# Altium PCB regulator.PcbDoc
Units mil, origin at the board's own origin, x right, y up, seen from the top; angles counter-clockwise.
Board outline 6000 x 4000 mil, 2 copper layers (Top Layer, Bottom Layer); 60 components, 45 nets, 228 pads, 31 vias.
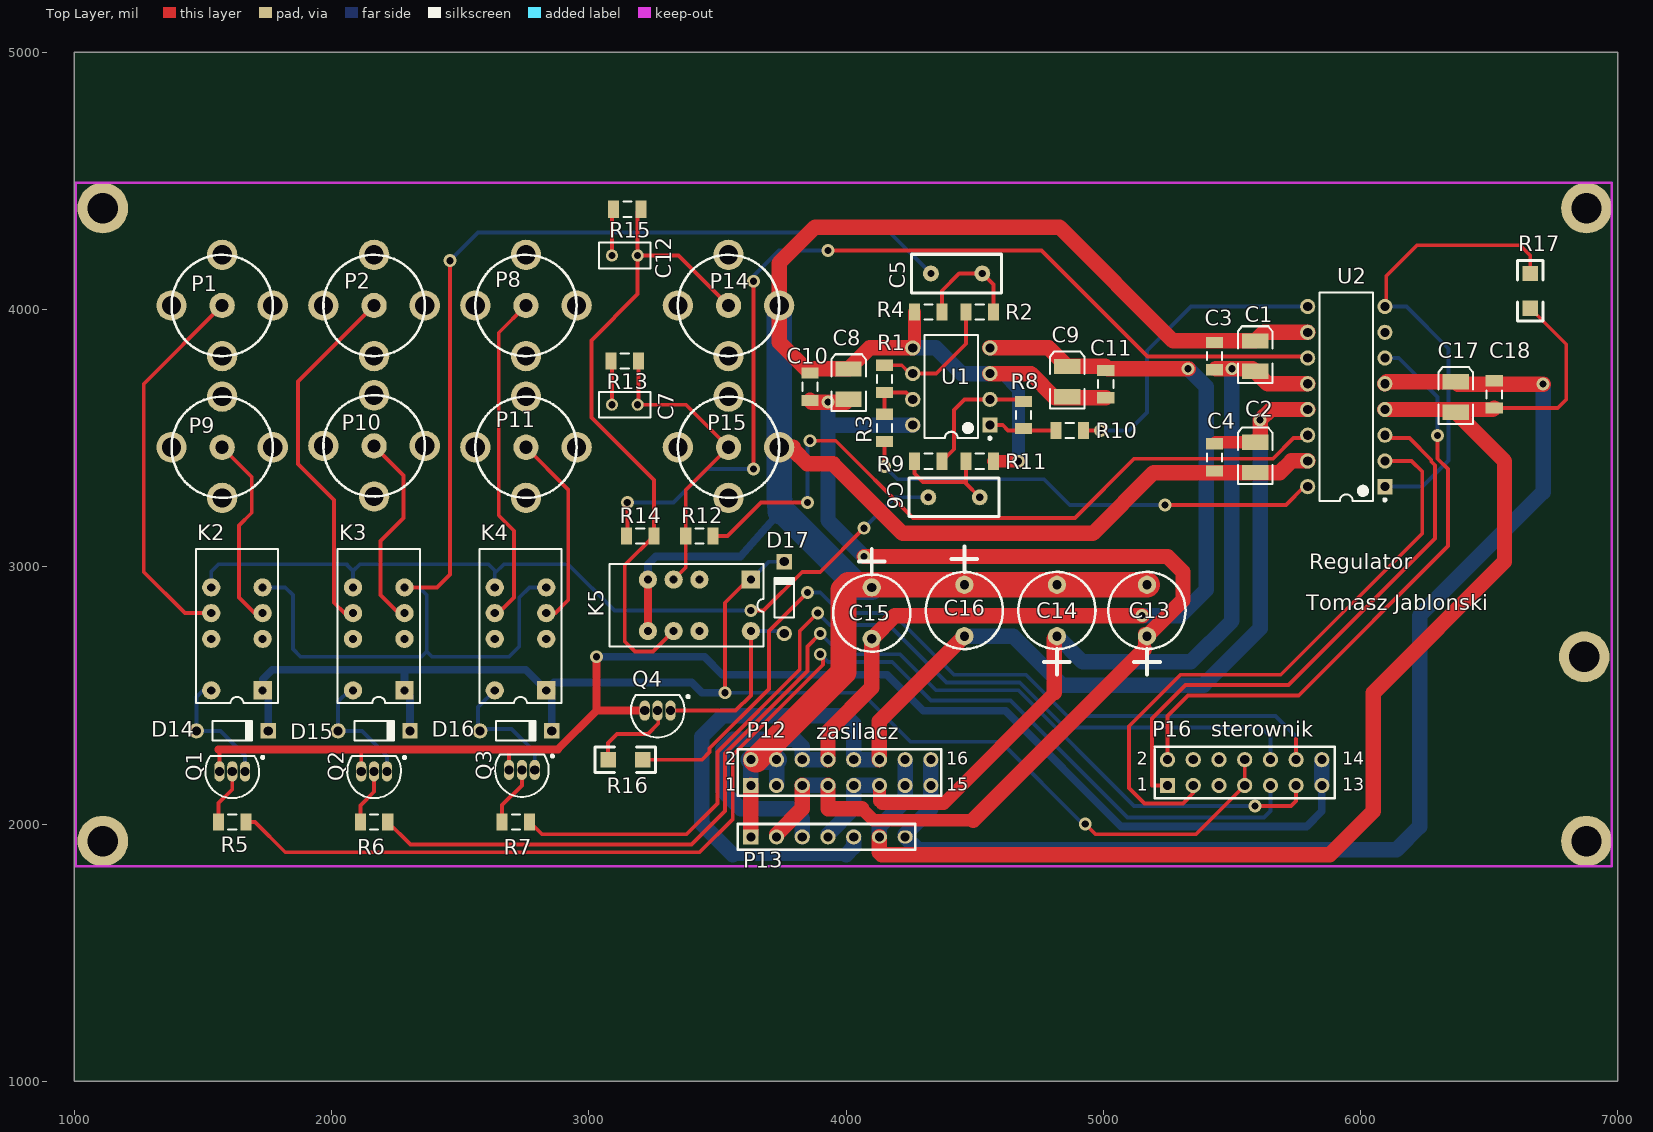
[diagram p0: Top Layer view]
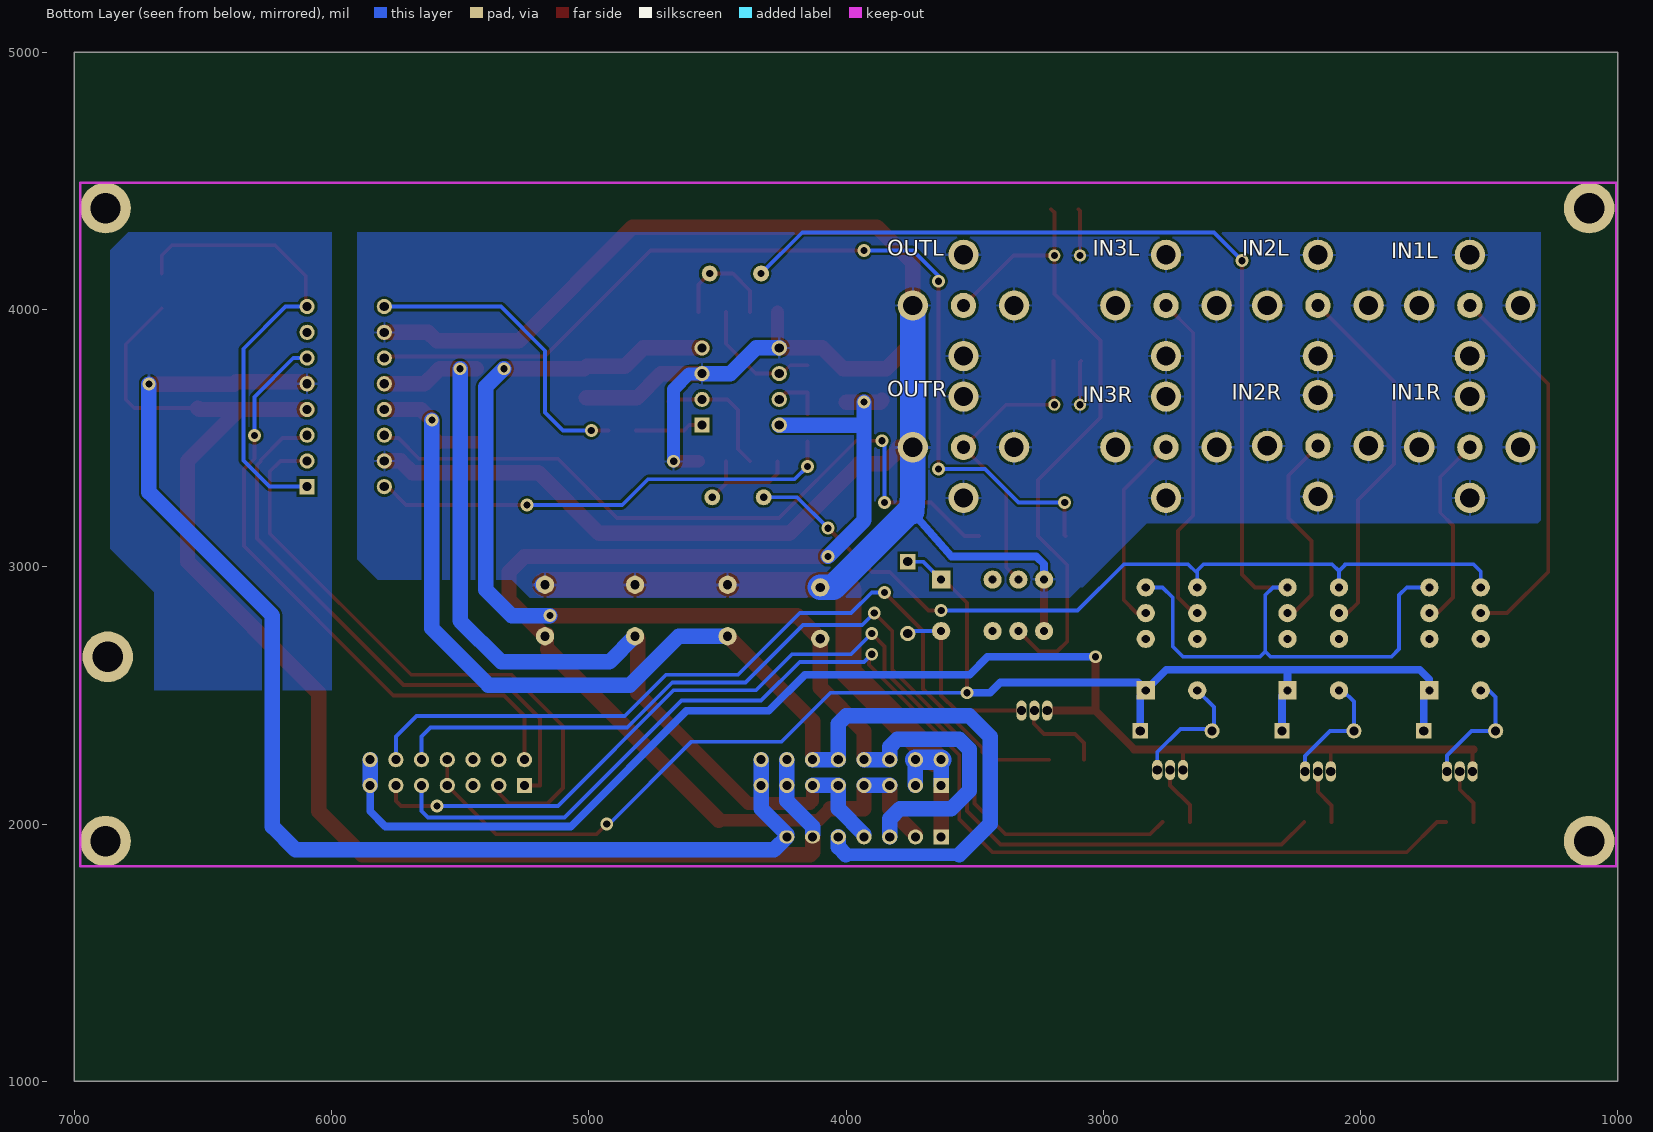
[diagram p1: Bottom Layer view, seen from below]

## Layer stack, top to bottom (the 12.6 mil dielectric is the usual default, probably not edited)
Top Solder: solder mask 0.4, Solder Resist, Dk 3.5
Top Layer: signal copper 1.4
Dielectric 1: dielectric 12.6, FR-4, Dk 4.8
Bottom Layer: signal copper 1.4
Bottom Solder: solder mask 0.4, Solder Resist, Dk 3.5

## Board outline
1000,1000 7000,1000 7000,5000 1000,5000

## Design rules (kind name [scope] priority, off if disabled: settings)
Clearance [All] p1: gap=10
PolygonConnect [All] p1: connectstyle=Relief reliefconductorwidth=10 reliefentries=4 polygonreliefangle="90 Angle" airgapwidth=10
RoomDefinition regulator [InComponentClass('regulator')] p1: confinementstyle=ConfineIn formatcopy=TRUE lockcomponents=FALSE outline 0,0 2000,0 2000,1000 0,1000
RoutingVias [All] p1: holewidth=28 width=50 viastyle="Through Hole" minholewidth=28 minwidth=50 maxholewidth=28 maxwidth=50
SolderMaskExpansion [All] p1: expansion=4
Width [All] p1: maxlimit=15 minlimit=15 preferedwidth=15
30 further rules are at their usual default settings.

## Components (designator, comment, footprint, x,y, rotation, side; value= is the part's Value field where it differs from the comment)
C1 "" 3.5X2.8X1.9 5590.55,3818.9 r90 top
C2 "" 3.5X2.8X1.9 5590.55,3425.2 r90 top
C3 "Cap" C1206 5433.07,3818.9 r90 top
C4 "Cap" C1206 5433.07,3425.2 r270 top
C5 "Cap" RAD0.2 4330,4140 r0 top
C6 "Cap" RAD0.2 4320,3270 r0 top
C7 "Cap" RAD-0.1 3140,3630 r0 top
C8 "" 3.5X2.8X1.9 4010,3710 r90 top
C9 "" 3.5X2.8X1.9 4860,3720 r90 top
C10 "Cap" C1206 3860,3700 r90 top
C11 "Cap" C1206 5010,3710 r270 top
C12 "Cap" RAD-0.1 3140,4210 r0 top
C13 "" RB.2/.3 5170,2730 r90 top
C14 "" RB.2/.3 4820,2730 r90 top
C15 "" RB.2/.3 4100,2920 r270 top
C16 "" RB.2/.3 4460,2930 r270 top
C17 "" 3.5X2.8X1.9 6370,3660 r90 top
C18 "Cap" C1206 6520,3670 r90 top
D14 "1N4148" DO-35 1614.17,2362.2 r0 top
D15 "1N4148" DO-35 2165.35,2362.2 r0 top
D16 "1N4148" DO-35 2716.54,2362.2 r0 top
D17 "1N4148" DO-35 3760,2880 r90 top
K2 "Relay-DPDT" Axicom_rel 1732.28,2519.68 r180 top
K3 "Relay-DPDT" Axicom_rel 2283.46,2519.68 r180 top
K4 "Relay-DPDT" Axicom_rel 2834.65,2519.68 r180 top
K5 "Relay-DPDT" Axicom_rel 3630,2950 r270 top
P1 "BNC" RCA_P 1574.8,4015.75 r0 top
P2 "BNC" RCA_P 2165.35,4015.75 r0 top
P8 "BNC" RCA_P 2755.91,4015.75 r0 top
P9 "BNC" RCA_P 1574.8,3464.57 r0 top
P10 "BNC" RCA_P 2165.35,3470 r0 top
P11 "BNC" RCA_P 2755.91,3464.57 r0 top
P12 "zasilacz" HDR2X8 3630,2150 r0 top
P13 "regulator" HDR1X7 3630,1950 r0 top
P14 "BNC" RCA_P 3543.31,4015.75 r0 top
P15 "BNC" RCA_P 3543.31,3464.57 r0 top
P16 "sterownik" HDR2X7 5250,2150 r0 top
Q1 "NPN" TO-226-AA 1614.17,2204.72 r90 top
Q2 "NPN" TO-226-AA 2165.35,2204.72 r90 top
Q3 "NPN" TO-226-AA 2740,2210 r90 top
Q4 "NPN" TO-226-AA 3267.72,2440.94 r90 top
R1 "Res2" C1206 4150,3730 r270 top
R2 "Res2" C1206 4520,3990 r180 top
R3 "Res2" C1206 4150,3540 r270 top
R4 "Res2" C1206 4320,3990 r0 top
R5 "Res2" C1206 1614.17,2007.87 r180 top
R6 "Res2" C1206 2165.35,2007.87 r180 top
R7 "Res2" C1206 2716.54,2007.87 r180 top
R8 "Res2" C1206 4690,3590 r270 top
R9 "Res2" C1206 4320,3410 r0 top
R10 "Res2" C1206 4870,3530 r0 top
R11 "Res2" C1206 4520,3410 r180 top
R12 "Res2" C1206 3430,3120 r0 top
R13 "Res2" C1206 3140,3800 r0 top
R14 "Res2" C1206 3200,3120 r180 top
R15 "Res2" C1206 3150,4390 r0 top
R16 "" 1206 3210,2250 r180 top
R17 "" 1206 6660,4140 r270 top
U1 "OPA2134PA" TI-P8 4409.45,3700.79 r180 top
U2 "PGA2311" DIP16 5944.88,3661.42 r180 top

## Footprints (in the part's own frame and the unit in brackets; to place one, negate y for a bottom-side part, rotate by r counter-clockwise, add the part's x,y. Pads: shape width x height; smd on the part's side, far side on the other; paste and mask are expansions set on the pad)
3.5X2.8X1.9 [mm] "SM LED; 2 C-Bend Leads; Body 3.5 x 2.8 x 1.9 mm, inc leads (LxWxH typ)"
  rect 1.5x2.6 smd: 1(-1.5,0) 2(1.5,0)
  silkscreen extent -2.65,-1.7 2.95,1.7
1206 [mil]
  rect 60x60 smd: 1(0,0) 2(135,0)
  silkscreen extent -50,-50 185,50
Axicom_rel [mm]
  round 1.8 hole 0.8: 1(0,-7.62) 2(0,-5.08) 3(0,-10.16) 4(5.08,-7.62) 5(5.08,-5.08) 6(5.08,-10.16) 8(5.08,0)
  rect 1.8x1.8 hole 0.8: 7(0,0)
  silkscreen extent -1.52,-13.97 6.6,1.27
C1206 [mm] "Chip Capacitor, Body 3.2x1.6mm, IPC High Density"
  rect 1.1x1.7 smd: 1(-1.35,0) 2(1.35,0)
  silkscreen extent -0.4,-0.75 0.4,0.75, body extent -1.7,-0.9 1.7,0.9, height 1.3
DIP16 [mm] "DIP, 16-Leads, Row Spacing 7.62mm, Pitch 2.54mm, Body 19.31x6.35mm"
  rect 1.5x1.5 hole 0.9: 1(-3.81,8.89)
  round 1.5 hole 0.9: 2(-3.81,6.35) 3(-3.81,3.81) 4(-3.81,1.27) 5(-3.81,-1.27) 6(-3.81,-3.81) 7(-3.81,-6.35) 8(-3.81,-8.89) 9(3.81,-8.89) 10(3.81,-6.35) 11(3.81,-3.81) 12(3.81,-1.27) 13(3.81,1.27) 14(3.81,3.81) 15(3.81,6.35) 16(3.81,8.89)
  silkscreen extent -3.94,-10.3 2.65,10.31, body extent -3.6,-10.28 3.6,10.28, height 4.42
DO-35 [mm] "Diode, Axial; Body 3.8 x 1.9 mm (LxDia. max), Lead Dia. 0.53 mm (max)"
  round 1.5 hole 0.9: 1(-3.55,0)
  rect 1.5x1.5 hole 0.9: 2(3.55,0)
  silkscreen extent -1.95,-0.95 2.05,0.95
HDR1X7 [mm] "Connector; Header; 7 Position"
  rect 1.5x1.5 hole 0.9: 1(0,0)
  round 1.5 hole 0.9: 2(2.54,0) 3(5.08,0) 4(7.62,0) 5(10.16,0)
  oval 1.5x1.3 hole 0.9: 6(12.7,0) 7(15.24,0)
HDR2X7 [mm] "Connector; Header; 7x2 Position"
  rect 1.5x1.5 hole 0.9: 1(0,0)
  round 1.5 hole 0.9: 2(0,2.54) 3(2.54,0) 4(2.54,2.54) 5(5.08,0) 6(5.08,2.54) 7(7.62,0) 8(7.62,2.54) 9(10.16,0) 10(10.16,2.54) 11(12.7,0) 12(12.7,2.54) 13(15.24,0) 14(15.24,2.54)
HDR2X8 [mm] "Connector; Header; 8x2 Position"
  rect 1.5x1.5 hole 0.9: 1(0,0)
  round 1.5 hole 0.9: 2(0,2.54) 3(2.54,0) 4(2.54,2.54) 5(5.08,0) 6(5.08,2.54) 7(7.62,0) 8(7.62,2.54) 9(10.16,0) 10(10.16,2.54) 11(12.7,0) 12(12.7,2.54) 13(15.24,0) 14(15.24,2.54) 15(17.78,0) 16(17.78,2.54)
RAD0.2 [mil]
  round 62 hole 28: 1(0,0) 2(200,0)
  silkscreen extent -75,-75 275,75
RAD-0.1 [mm] "Radial Cap, Thru-Hole; 2 Leads; 0.1 in Pin Spacing"
  round 1.2 hole 0.7: 1(-1.27,0) 2(1.27,0)
  silkscreen extent -2.54,-1.27 2.54,1.27
RB.2/.3 [mm]
  round 1.8 hole 0.9: 1(0,0) 2(5.08,0)
  silkscreen extent -3.81,-3.81 6.35,3.81
RCA_P [mm]
  round 2.5 hole 1.3: 1(0,0)
  round 3 hole 1.9: 2(-5,0) 2(0,-5) 2(0,5) 2(5,0)
  silkscreen extent -5,-5 5,5
TI-P8 [mm] "DIP, 8-Leads, Body 9.59x6.35mm, Pitch 2.54mm"
  rect 1.5x1.5 hole 0.9: 1(-3.81,3.81)
  round 1.5 hole 0.9: 2(-3.81,1.27) 3(-3.81,-1.27) 4(-3.81,-3.81) 5(3.81,-3.81) 6(3.81,-1.27) 7(3.81,1.27) 8(3.81,3.81)
  silkscreen extent -3.94,-5.1 2.65,5.23, body extent -3.95,-5.07 3.95,5.07, height 5.08
TO-226-AA [mm] "TO, Flat Index; 3 In-Line, Axial Leads; Body Dia. 4.8mm; Leads 0.55 x 0.51 mm (max)"
  oval 2x1 hole 0.9: 1(0,-1.27) 2(0,0) 3(0,1.27)
  silkscreen extent -2.65,-3.13 1.52,2.65, body extent -2.66,-2.66 1.52,2.66, height 5.33

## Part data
C1 C2 C8 C9 C13 C14 C15 C16 C17: library part ELECTRO2, "Electrolytic Capacitor"
C3 C4 C5 C6 C7 C10 C11 C12 C18: "Capacitor"
D14 D15 D16 D17: library part "Diode 1N4148", "High Conductance Fast Diode"
K2 K3 K4 K5: "Dual-Pole Dual-Throw Relay"
P1 P2 P8 P9 P10 P11 P14 P15: "BNC Elbow Connector"
P12: library part "Header 8X2", "Header, 8-Pin, Dual row"
P13: library part MHDR1X7, "Header, 7-Pin"
P16: library part "Header 7X2", "Header, 7-Pin, Dual row"
Q1 Q2 Q3 Q4: "NPN Bipolar Transistor"
R1 R2 R3 R4 R5 R6 R7 R8 R9 R10 R11 R12 R13 R14 R15: "Resistor"
R16 R17: library part Res2, "Resistor"
U1: "SoundPlus(TM) High Performance Audio Operational Amplifier, 5 to 36 V, -40 to 125 degC, 8-pin DIP (P8), Green (RoHS & no Sb/Br)"

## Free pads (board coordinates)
  round 196.85 hole 118.11: 0(1110.83,1933.62) 0(1110.83,4394.25) 0(6870,2650) 0(6878.54,1933.62) 0(6878.54,4394.25)

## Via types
v1: diameter 50, hole 28, Top Layer to Bottom Layer, 31 vias

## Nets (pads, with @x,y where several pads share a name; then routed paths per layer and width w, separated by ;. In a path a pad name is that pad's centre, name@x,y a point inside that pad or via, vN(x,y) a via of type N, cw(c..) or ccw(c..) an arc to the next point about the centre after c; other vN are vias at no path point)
+5V: D14.2 D15.2 D16.2 D17.2 K2.7 K3.7 K4.7 K5.7 P16.7 P16.8 | length 5550.7
  Top Layer w15: v1(3530,2510) 3530,2860 3620,2950 v1(3630,2950) ; v1(4930,2000) 4970,1960 5360,1960 P16.7 P16.8
  Bottom Layer w15: K2.7 K2.7@1753.94,2498.03 ; K3.7 K3.7@2305.12,2498.03 ; v1(3530,2510) 4060,2510 4250,2320 4600,2320 4925,1995 v1(4930,2000) ; v1(3630,2950) 3630.47,2950 3700.24,3019.76 D17.2 ; P16.8@5550,2240 P16.8
  Bottom Layer w30: K2.7 1732.28,2562.28 1770,2600 2754.33,2600 K4.7 2864.96,2550 3400,2550 3440,2510 v1(3530,2510) ; D14.2 K2.7@1753.94,2498.03 ; K3.7 2283.46,2596.54 ; D15.2 K3.7@2305.12,2498.03 ; D16.2 K4.7@2856.3,2498.03
+5VA: C1.1 C3.1 C14.1 P12.9 P12.11 P13.4 U2.12 | length 3627.3
  Top Layer w50: P12.11 4130,2090 4140,2080 4380,2080 4810,2510
  Top Layer w60: 4810,2510 4810,2720 C14.1 ; C3.1@5437.32,3770 v1(5500,3770) 5580.39,3770 C1.1 5638.98,3711.42 U2.12
  Bottom Layer w60: P13.4@3930,1960 4030,2060 P12.9 P12.11 ; C14.1 4920,2630 5340,2630 5500,2790 v1(5500,3770)
+5VDA: C17.1 C18.1 P12.13 P12.14 P13.6 R17.2 U2.4 | length 5360.8
  Top Layer w15: C18.1 6766.85,3616.85 6800,3650 6800,3865 R17.2
  Top Layer w60: P13.6 4130,1890 4139.8,1880.2 5880.2,1880.2 6050.15,2050.15 6050.15,2510.15 6560,3020 6560,3410.94 C17.1 ; U2.4 6514.57,3611.42 C18.1
  Bottom Layer w60: P13.6@4130,1960 4130,1990 4230,2090 P12.13 P12.14
+12VA: C8.1 C10.1 C13.1 P12.5 P12.7 P13.2 U1.8 | length 4711.9
  Top Layer w50: 4061.01,2060 4106.48,2014.53 4494.53,2014.53 ; 5160,2680 C13.1@5160,2740
  Top Layer w60: P13.2@3730,1960 3830,2060 P12.5 ; C10.1 3866.85,3640 v1(3930,3640) C8.1@3999.05,3640 ; P12.7 3930,2060 4061.01,2060 ; v1(4070,3040) 5250,3040 5310,2980 5310,2870 C13.1 ; 4494.53,2014.53 5160,2680
  Bottom Layer w15: 3930,3560 3939.21,3550.79
  Bottom Layer w60: P12.5 P12.7 ; v1(3930,3640) 3930,3560 3930,3180 v1(4070,3040) ; 3939.21,3550.79 U1.8
-5VA: C2.2 C4.1 C16.2 P12.10 P12.12 P13.5 U2.13 | length 5109.4
  Top Layer w15: C4.1 C4.1@5438.98,3484.25
  Top Layer w50: C4.1@5438.98,3484.25 C2.2
  Top Layer w60: P12.12 4130,2400 C16.2 ; C2.2 5610,3503.7 v1(5610,3570) 5651.42,3611.42 U2.13
  Bottom Layer w50: 3560.47,1880.2 4000.2,1880.2
  Bottom Layer w60: 3560.47,1880.2 3440,2000.67 3440,2340 3520,2420 4000,2420 4030,2390 P12.10 P12.12 ; 4000.2,1880.2 4030,1910 P13.5 ; C16.2 4650,2730 4840,2540 5390,2540 5610,2760 v1(5610,3570)
-12VA: C9.2 C11.1 C15.2 P12.6 P12.8 P13.3 U1.4 | length 4686.7
  Top Layer w60: P12.8 3930,2360 4100,2530 C15.2 4190,2810 v1(5151.01,2810) ; U1.4 4788.27,3850.79 C9.2 5007.8,3779.06 5016.85,3770 v1(5330,3770)
  Bottom Layer w60: P13.3 3830,2020 3790,2060 3590,2060 3520,2130 3520,2290 3560,2330 3800,2330 3830,2300 P12.6 P12.8 ; v1(5151.01,2810) 5300,2810 5400,2910 5400,3700 v1(5330,3770)
ADGND: C17.2 C18.2 P12.15 P12.16 P13.7 U2.5 | length 4930.3
  Top Layer w60: U2.5 6102.52,3719.06 C17.2 6379.06,3710 v1(6710,3710)
  Bottom Layer w60: P13.7 4280,1900 6140,1900 6230,1990 6230,2810 6710,3290 v1(6710,3710) ; P13.7@4230,1960 4330,2060 P12.15 P12.16
AGND: C1.2 C2.1 C3.2 C4.2 C7.1 C8.2 C9.1 C10.2 C11.2 C12.1 C13.2 C14.2 C15.1 C16.1 K5.3 K5.6 P1.2 P2.2 P8.2 P9.2 P10.2 P11.2 P12.1 P12.2 P12.3 P12.4 P13.1 P14.2 P15.2 R4.1 R11.1 R13.1 R15.1 U1.3 U1.5 U2.10 U2.15 | length 12006.4
  Top Layer w15: R13.1 3090,3796.85 C7.1 ; C12.1 3090,4383.15 R15.1 ; U1.5 U1.5@4266.85,3858.19
  Top Layer w30: K5.6 K5.3
  Top Layer w50: U1.5@4266.85,3858.19 R4.1 ; R11.1 v1(4670,3410)
  Top Layer w60: P13.1@3630,1960 P12.1 ; P15.2@3740.16,3464.57 3795,3464.57 3795,3455 3850,3400 3950,3400 4220,3130 4960,3130 5196.14,3366.14 C2.1 5686.14,3366.14 5731.42,3411.42 U2.15 ; U1.5 4091.73,3850.79 C8.2 3844.09,3769.06 3740.16,3872.99 3740.16,4015.75 3740.16,4180.16 3880,4320 4830,4320 5272.05,3877.95 C1.2 5624.02,3911.42 U2.10 ; U1.3 4719.21,3750.79 4813.15,3656.85 C11.2
  Top Layer w100: P12.2@3650,2250 3990,2590 3990,2910 4010,2930 C16.1 C14.2 C13.2
  Bottom Layer w15: U1.3 U1.3@4560.24,3750
  Bottom Layer w30: K5.3 3230,3010 3260,3040 3590,3040 3749.7,3220.3
  Bottom Layer w50: U1.3@4560.24,3750 4610,3750 4670,3690 4670,3480 v1(4670,3410)
  Bottom Layer w60: P12.1 P12.2 ; P12.3 P12.4 ; U1.5 4349.21,3850.79 4449.21,3750.79 U1.3 ; C13.2 C13.2@5180,2930
  Bottom Layer w80: P12.2 P12.4
  Bottom Layer w100: P14.2@3740.16,4015.75 3740.16,3464.57 3740.16,3279.84 3745,3215 ; 3749.7,3220.3 4050,2920 C15.1
CSI: P16.3 U2.2 | length 2424.4
  Top Layer w15: P16.3 5350,2120 5310,2080 5160,2080 5100,2140 5100,2380 5300,2580 5690,2580 6240,3130 6240,3370 6198.58,3411.42 U2.2
  Bottom Layer w15: P16.3 P16.3@5350,2160
GND: P16.13 P16.14 Q1.3 Q2.3 Q3.3 Q4.3 | length 5501.3
  Top Layer w15: 1560,2290 1564.17,2285.83 Q1.3 ; Q2.3 2115.35,2285.35 2120,2290 ; Q3.3 2690,2290
  Top Layer w30: 1560,2290 2120,2290 2690,2290 2880,2290 3030,2440 v1(3030,2650) ; 3030.94,2440.94 Q4.3
  Bottom Layer w30: v1(3030,2650) 3450,2650 3519.29,2580.71 4159.29,2580.71 4300,2440 4620,2440 5070,1990 5790,1990 5850,2050 P16.13
  Bottom Layer w60: P16.13 P16.14
IN1L: K2.1 P9.1 | length 770.3
  Top Layer w15: P9.1 1690,3349.37 1690,3210 1640,3160 1640,2880 1700,2820 1731.97,2820 K2.1
IN1R: K2.4 P1.1 | length 1490.7
  Top Layer w15: K2.4 1430.32,2819.68 1270,2980 1270,3710.94 P1.1
IN2L: K3.1 P10.1 | length 787.4
  Top Layer w15: P10.1 2280,3355.35 2280,3190 2190,3100 2190,2890 2260.32,2819.68 K3.1
IN2R: K3.4 P2.1 | length 1426.2
  Top Layer w15: K3.4 2050.32,2819.68 2010,2860 2010,3260 1870,3400 1870,3720.39 P2.1
IN3L: K4.1 P11.1 | length 768.7
  Top Layer w15: P11.1 2920,3300.47 2920,2870 2870,2820 2834.96,2820 K4.1
IN3R: K4.4 P8.1 | length 1304.8
  Top Layer w15: K4.4 2649.68,2819.68 2710,2880 2710,3140 2650,3200 2650,3909.84 P8.1
INL: C5.1 K2.3 K3.3 K4.3 | length 5295
  Top Layer w15: K3.3 2409.68,2919.68 2460,2970 v1(2460,4190)
  Bottom Layer w15: K2.3 1732.6,2920 1820,2920 1850,2890 1850,2680 1880,2650 2350,2650 2370,2670 ; K3.3 2340.32,2919.68 2370,2890 2370,2670 ; v1(2460,4190) 2570,4300 4170,4300 C5.1 ; K4.3 2769.68,2919.68 2730,2880 2730,2690 2690,2650 2390,2650 2370,2670
INL1: R3.2 U2.16 | length 1833.4
  Top Layer w15: v1(4150,3390) R3.2 ; v1(5240,3240) 5710,3240 5781.42,3311.42 U2.16
  Bottom Layer w15: v1(4150,3390) 4200,3340 4770,3340 4870,3240 v1(5240,3240)
INR: C6.1 K2.6 K3.6 K4.6 | length 3296.7
  Top Layer w15: v1(3630,2830) 3680,2830 3830,2980 3900,2980 v1(4070,3150)
  Bottom Layer w15: K2.6 1532.28,2982.28 1560,3010 2060,3010 2060,3006.93 2083.46,2983.46 ; K3.6 2083.46,2983.46 ; K4.6 2634.65,2974.65 ; v1(3630,2830) 3100,2830 2920,3010 2670,3010 2634.65,2974.65 ; v1(4070,3150) 4190,3270 C6.1 ; 2083.46,2983.46 2110,3010 2610,3010 2634.65,2985.35 2634.65,2974.65
INR1: R10.2 U2.9 | length 1211.7
  Top Layer w15: R10.2 v1(4990,3530)
  Bottom Layer w15: v1(4990,3530) 5100,3530 5170,3600 5170,3840 5341.42,4011.42 U2.9
MUTE: P16.12 R16.1 | length 3351.8
  Top Layer w15: R16.1 3440,2250 3470,2280 3470,2294.64 3700,2524.64 3700,2750 v1(3850,2900) ; P16.12 5750,2330
  Bottom Layer w15: v1(3850,2900) 3900,2900 3980,2820 4180,2820 4420,2580 4700,2580 4860,2420 5670,2420 5750,2340 P16.12
NetC5_2: C5.2 R2.1 R4.2 | length 435.6
  Top Layer w15: R4.2 4373.15,4073.15 4440,4140 C5.2 4573.15,4096.85 R2.1
NetC6_2: C6.2 R9.1 R11.2 | length 422.6
  Top Layer w15: R9.1 4266.85,3363.15 4300,3330 4466.85,3330 ; R11.2 4466.85,3330 ; C6.2 4466.85,3323.15 4466.85,3330
NetC7_2: C7.2 K5.1 P15.1 R12.1 R13.2 | length 1196.1
  Top Layer w15: R13.2 3193.15,3633.15 C7.2 3377.87,3630 P15.1 3376.85,3298.11 R12.1 3376.85,2996.85 K5.1
NetC12_2: C12.2 K5.4 P14.1 R14.1 R15.2 | length 2581.1
  Top Layer w15: R15.2 3190,4376.85 C12.2 ; K5.4 3250,2670 3180,2670 3140,2710 3140,3006.85 R14.1 3253.15,3336.85 3010,3580 3010,3880 3190,4060 C12.2 ; P14.1 3349.06,4210 C12.2
NetD14_1: D14.1 K2.8 Q1.1 | length 491.3
  Bottom Layer w15: K2.8 1499.68,2519.68 1474.41,2494.41 D14.1 1567.8,2362.2 1664.17,2265.83 Q1.1
NetD15_1: D15.1 K3.8 Q2.1 | length 479.6
  Bottom Layer w15: K3.8 2069.68,2519.68 2025.59,2475.59 D15.1 2117.8,2362.2 2215.35,2264.65 Q2.1
NetD16_1: D16.1 K4.8 Q3.1 | length 495.2
  Bottom Layer w15: K4.8 2570,2455.04 2570,2384.57 2584.57,2370 2700,2370 2790,2280 Q3.1
NetD17_1: D17.1 K5.8 Q4.1 | length 720.8
  Top Layer w15: Q4.1 3570.94,2440.94 3630,2500 K5.8 ; D17.1@3750.24,2750 D17.1
  Bottom Layer w15: K5.8 D17.1@3750.24,2750
NetQ1_2: Q1.2 R5.2 | length 218.9
  Top Layer w15: R5.2 1561.02,2081.02 1614.17,2134.17 Q1.2
NetQ2_2: Q2.2 R6.2 | length 218.9
  Top Layer w15: R6.2 2112.2,2072.2 2165.35,2125.35 Q2.2
NetQ3_2: Q3.2 R7.2 | length 233.9
  Top Layer w15: R7.2 2663.39,2073.39 2740,2150 Q3.2
NetQ4_2: Q4.2 R16.2 | length 343
  Top Layer w15: R16.2 3075,2315 3110,2350 3230,2350 3270,2390 3270,2438.66 Q4.2
NetR1_1: R1.1 R2.2 U1.6 | length 501.5
  Top Layer w15: R1.1 4216.85,3783.15 4249.21,3750.79 U1.6 4350.79,3750.79 4466.85,3866.85 R2.2
NetR1_2: R1.2 R3.1 U1.7 | length 203.9
  Top Layer w15: R3.1 R1.2 4233.39,3676.85 U1.7
NetR8_1: R8.1 R9.2 U1.2 | length 509.5
  Top Layer w15: R9.2 4420,3456.85 4420,3610 4460.79,3650.79 U1.2 4682.36,3650.79 R8.1
NetR8_2: R8.2 R10.1 U1.1 | length 266
  Top Layer w15: U1.1 4609.21,3550.79 4630,3530 R10.1
NetR17_1: R17.1 U2.1 U2.8 | length 1863.2
  Top Layer w15: U2.8@6100,4010 6100,4130 6220,4250 6620,4250 6660,4210 R17.1
  Bottom Layer w15: U2.8@6090,4016.3 U2.8 6178.58,4011.42 6342.5,3847.5 6342.5,3412.5 6241.42,3311.42 U2.1
OUTL: R12.2 U2.14 | length 2863
  Top Layer w15: R12.2 3540,3120 3670,3250 v1(3850,3250) ; v1(3860,3490) 3960,3490 4260,3190 4890,3190 5120,3420 5660,3420 5740,3500 5783.46,3500 U2.14
  Bottom Layer w15: v1(3850,3250) v1@3850,3500
OUTR: R14.2 U2.11 | length 3798.4
  Top Layer w15: R14.2 3150,3123.15 v1(3150,3250) ; v1(3640,3380) v1(3640,4110) ; v1(3930,4230) 4760,4230 5172.5,3817.5 5794.88,3817.5 U2.11
  Bottom Layer w15: v1(3150,3250) 3330,3250 3460,3380 v1(3640,3380) ; v1(3640,4110) 3640,4130 3740,4230 v1(3930,4230)
SCKI: P16.2 U2.6 | length 2397.8
  Top Layer w15: P16.2 5250,2420 5330,2500 5760,2500 6340,3080 6340,3380 6300,3420 v1(6300,3510)
  Bottom Layer w15: U2.6 6148.58,3811.42 6300,3660 v1(6300,3510)
SDOI: P16.1 U2.3 | length 2241.2
  Top Layer w15: v1(5250,2150) 5190,2150 5190,2410 5320,2540 5720,2540 6290,3110 6290,3394.64 6275,3409.64 6275,3415 6190,3500 U2.3@6106.3,3500
  Bottom Layer w15: U2.3 U2.3@6106.3,3500
SEL1: P16.9 R5.1 | length 4893.7
  Top Layer w15: R5.1 1702.13,2007.87 1820,1890 3430,1890 3560,2020 3560,2269.29 3910,2619.29 v1@3910,2650
  Bottom Layer w15: v1(3900,2660) 3930,2630 4180,2630 4330,2480 4640,2480 5095,2025 5625,2025 5650,2050 P16.9
SEL2: P16.11 R6.1 | length 4440.8
  Top Layer w15: R6.1 2306.38,1920 3400,1920 3530,2050 3530,2274.64 3850,2594.64 3850,2690 v1(3900,2740) ; v1(5590,2070) 5730,2070 5750,2090 P16.11
  Bottom Layer w15: v1(3900,2740) 3980,2660 4210,2660 4350,2520 4670,2520 5120,2070 v1(5590,2070)
SEL3: P16.10 R7.1 | length 3750.2
  Top Layer w15: R7.1 2817.56,1960 3380,1960 3500,2080 3500,2280 3820,2600 3820,2750 v1(3890,2820)
  Bottom Layer w15: v1(3890,2820) 3937.07,2772.93 4167.07,2772.93 4390,2550 4675.36,2550 4850.36,2375 5615,2375 5650,2340 P16.10
pads on no net: K2.2 K2.5 K3.2 K3.5 K4.2 K4.5 K5.2 K5.5 P16.4 P16.5 P16.6 U2.7

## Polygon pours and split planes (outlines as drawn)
ADGND on Bottom Layer "Top Layer-No Net" (solid, pour order 4): 6000,4300 6000,2520 6690,2520 6690,2840 6690,2900 6860,3070 6860,4230 6790,4300 6000,4300
AGND on Bottom Layer "Top Layer-No Net" (solid, pour order 4): 1300,4300 5900,4300 5900,3070 5900,3030 5820,2950 5300,2950 5230,2880 3130,2880 3090,2920 3080,2920 2830,3170 1310,3170 1300,3180 1300,4300

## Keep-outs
Keep-Out Layer:
  lines w10: 1005,1835.2 1005,4492.68 6976.97,4492.68 6976.97,1835.2 1005,1835.2

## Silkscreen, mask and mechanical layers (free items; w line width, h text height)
Top Overlay:
  lines w10: 5200,2290 5200,2100 5890,2100 5900,2100 5900,2300 5200,2300 ; 3580,1900 3580,2000 4270,2000 4270,1900 3580,1900 ; 3580,2110 3580,2290 4370,2290 4370,2110 3580,2110
  text "Regulator" at 5800,2990 h60
  text "Tomasz Jablonski" at 5790,2830 h60
Bottom Overlay:
  text "IN2L" at 2460,4210 h60
  text "IN3L" at 3040,4210 h60
  text "OUTL" at 3840,4210 h60
  text "IN1L" at 1880,4200 h60
  text "OUTR" at 3840,3660 h60
  text "IN1R" at 1880,3650 h60
  text "IN2R" at 2500,3650 h60
  text "IN3R" at 3080,3640 h60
